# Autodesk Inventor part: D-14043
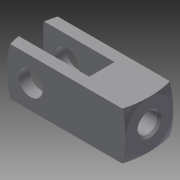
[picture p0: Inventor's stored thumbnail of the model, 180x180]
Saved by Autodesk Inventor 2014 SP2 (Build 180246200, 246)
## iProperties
Created: 2020-01
Part Number: D-14043
Material: Generic
Catalog Web Link: www.cadenas.de
Description: Piston Rod Clevis for Original Line Cylinders - Body-
Vendor: BIMBA
Document SubType Name: Modeling
Designer: psadmin
Manufacturer: BIMBA
Mass: 1.26173 g
Surface Area: 12.864 cm^2
Volume: 1.26173 cm^3
Density: 1 g/cm^3
Appearance: PSOLRGB-191-191-191
Category: PARTsolutions
Company: BIMBA
Title: D-14043
Author: Cadenas PARTsolutions
PSOL_IDENT_0: {$CADENAS_DATA\23d-libs\bimba\bimba_brand\bimba_imperial\bimba_full_line\original_line_cylinders\acc
PSOL_IDENT_1: essories\piston_rod_clevis_body.prj},201 {VTYP=3D},{NB=D-14043},{LINA=D-14043},{NN=Piston Rod Clevis
PSOL_IDENT_2: for Original Line Cylinders - Body},{DATE=23.12.2019 10:36:51},{GEOMDATE=06.12.2012 07:16:06},{VERS
PSOL_IDENT_3: ION=},{LINEID=190},{WBVAR=},{WBNUMERIC=}  {NB=D-14043},{LINA=D-14043},{KT=DUMMY},{PN=D-14043},{L=0.9
PSOL_IDENT_4: 3700000},{L1=0.75000000},{L2=0.37500000},{W=0.20000000},{W1=0.37500000},{DIA1=0.19000000},{DIA1CS=0.
PSOL_IDENT_5: 00000000},{DIA2=0.37500000},{DIA3=0.15620000},{CS=90.00000000},{CDP=0.03000000},{AN=30.00000000},{ND
PSOL_IDENT_6: M=0.19000000},{CODE=UNF},{NDMDP=0.31000000},{COLOR=0.75,0.75,0.75,0.00}
NN: Piston Rod Clevis for Original Line Cylinders - Body
NB: D-14043
NBSYN: $PN.
LINA: D-14043
PN: D-14043
L: 0.937
L1: 0.75
L2: 0.375
W: 0.2
W1: 0.375
DIA1: 0.19
DIA1CS: 0
DIA2: 0.375
DIA3: 0.1562
CS: 90
CDP: 0.03
AN: 30
NDM: 0.19
CODE: UNF
NDMDP: 0.31
SUPPLIER: BIMBA
ARTICLENO: D-14043
BOMINFO: D-14043
CREATOR: CADENAS GmbH
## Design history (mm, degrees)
sketch "Sketch_1"
  geometry: L1 (-4.75, -4.763)-(19.05, -4.763); L2 (19.05, -4.763)-(19.05, 4.763); L3 (19.05, 4.763)-(-4.75, 4.763); L4 (-4.75, 4.763)-(-4.75, -4.763)
  constraints: 8 end point
extrude "Extrusion1" join sketch "Sketch_1" stored distance "d0" = 9.525; taper "d1" = 0 deg
sketch "Sketch_2"
  geometry: L1 (4.75, 2.54)-(-9.525, 2.54); L2 (-9.525, 2.54)-(-9.525, -2.54); L3 (-9.525, -2.54)-(4.75, -2.54); L4 (4.75, -2.54)-(4.75, 2.54)
  constraints: 8 end point
extrude "Extrusion2" cut sketch "Sketch_2" stored distance "d2" = 9.525; taper "d3" = 0 deg
sketch "Sketch_3"
  geometry: L1 (19.05, 0)-(11.176, 0); L2 (11.176, 0)-(11.176, 1.984); L3 (11.176, 1.984)-(18.621, 1.984); L4 (18.621, 1.984)-(19.05, 2.413); L5 (19.05, 2.413)-(19.05, 0); L6 (19.05, 0)-(11.176, 0)
  constraints: 12 end point
revolve "Revolution1" sketch "Sketch_3" stored, may be unused: angle "d4" = 360 deg
sketch "Sketch5"
  geometry: 1 further point
hole "Hole1" sketch "Sketch5" at (0, 0) diameter "d5" = 3.96748; stored, may be unused: countersink angle "d9" = 82 deg, drill point angle "d11" = 0 deg; dims "d6" = 19.05, "d7" = 9.525, "d8" = 6.35, "d10" = 1.651
sketch "Sketch6"
  geometry: 1 further point
hole "Hole2" sketch "Sketch6" at (0, 0) diameter "d12" = 4.826; stored, may be unused: countersink angle "d16" = 82 deg, drill point angle "d18" = 0 deg; dims "d13" = 19.05, "d14" = 9.525, "d15" = 6.35, "d17" = 9.525
sketch "Sketch_9"
  geometry: L1 (23.812, 0)-(19.05, 0); L2 (19.05, 0)-(19.05, 4.763); L3 (16.51, 9.525)-(23.812, 9.525); L4 (23.812, 9.525)-(23.812, 0); L5 (23.812, 0)-(19.05, 0); A1 r 10.474 centre (8.85, 2.381) between (19.05, 4.763) and (16.51, 9.525)
  constraints: 10 end point, 2 point on circle, 1 centre point
revolve "Revolution2" sketch "Sketch_9" stored, may be unused: angle "d19" = 360 deg
sketch "Sketch_10"
  geometry: L1 (-4.75, 0)-(-9.512, 0); L2 (-9.512, 0)-(-9.512, 9.525); L3 (-9.512, 9.525)-(-2.21, 9.525); L4 (-4.75, 4.763)-(-4.75, 0); L5 (-4.75, 0)-(-9.512, 0); A1 r 10.474 centre (5.45, 2.381) between (-2.21, 9.525) and (-4.75, 4.763)
  constraints: 10 end point, 2 point on circle, 1 centre point
revolve "Revolution3" sketch "Sketch_10" stored, may be unused: angle "d20" = 360 deg
node "dummy_XY"
node "dummy_YZ"
node "dummy_ZX"
node "dummy_X"
node "dummy_Y"
node "dummy_Z"
node "dummy_Center"
node "h1_XY"
node "h1_YZ"
node "h1_ZX"
node "h1_X"
node "h1_Y"
node "h1_Z"
node "h1_Center"
node "h2_XY"
node "h2_YZ"
node "h2_ZX"
node "h2_X"
node "h2_Y"
node "h2_Z"
node "h2_Center"
node "l1_XY"
node "l1_YZ"
node "l1_ZX"
node "l1_X"
node "l1_Y"
node "l1_Z"
node "l1_Center"
node "l11_XY"
node "l11_YZ"
node "l11_ZX"
node "l11_X"
node "l11_Y"
node "l11_Z"
node "l11_Center"
node "l12_XY"
node "l12_YZ"
node "l12_ZX"
node "l12_X"
node "l12_Y"
node "l12_Z"
node "l12_Center"
node "l2_XY"
node "l2_YZ"
node "l2_ZX"
node "l2_X"
node "l2_Y"
node "l2_Z"
node "l2_Center"
node "l21_XY"
node "l21_YZ"
node "l21_ZX"
node "l21_X"
node "l21_Y"
node "l21_Z"
node "l21_Center"
node "l22_XY"
node "l22_YZ"
node "l22_ZX"
node "l22_X"
node "l22_Y"
node "l22_Z"
node "l22_Center"
node "piston_rod_clevis_XY"
node "piston_rod_clevis_YZ"
node "piston_rod_clevis_ZX"
node "piston_rod_clevis_X"
node "piston_rod_clevis_Y"
node "piston_rod_clevis_Z"
node "piston_rod_clevis_Center"
node "rod_clevis_body_XY"
node "rod_clevis_body_YZ"
node "rod_clevis_body_ZX"
node "rod_clevis_body_X"
node "rod_clevis_body_Y"
node "rod_clevis_body_Z"
node "rod_clevis_body_Center"
node "th1_XY"
node "th1_YZ"
node "th1_ZX"
node "th1_X"
node "th1_Y"
node "th1_Z"
node "th1_Center"
node "th2_XY"
node "th2_YZ"
node "th2_ZX"
node "th2_X"
node "th2_Y"
node "th2_Z"
node "th2_Center"
node "to_cylinder_XY"
node "to_cylinder_YZ"
node "to_cylinder_ZX"
node "to_cylinder_X"
node "to_cylinder_Y"
node "to_cylinder_Z"
node "to_cylinder_Center"
node "w1_XY"
node "w1_YZ"
node "w1_ZX"
node "w1_X"
node "w1_Y"
node "w1_Z"
node "w1_Center"
node "w11_XY"
node "w11_YZ"
node "w11_ZX"
node "w11_X"
node "w11_Y"
node "w11_Z"
node "w11_Center"
node "w12_XY"
node "w12_YZ"
node "w12_ZX"
node "w12_X"
node "w12_Y"
node "w12_Z"
node "w12_Center"
node "w2_XY"
node "w2_YZ"
node "w2_ZX"
node "w2_X"
node "w2_Y"
node "w2_Z"
node "w2_Center"
body "Solid1"
other parameters: "d21" = 0, "d22" = 0
